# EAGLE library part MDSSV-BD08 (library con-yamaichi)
YAMAICHI CONNECTOR
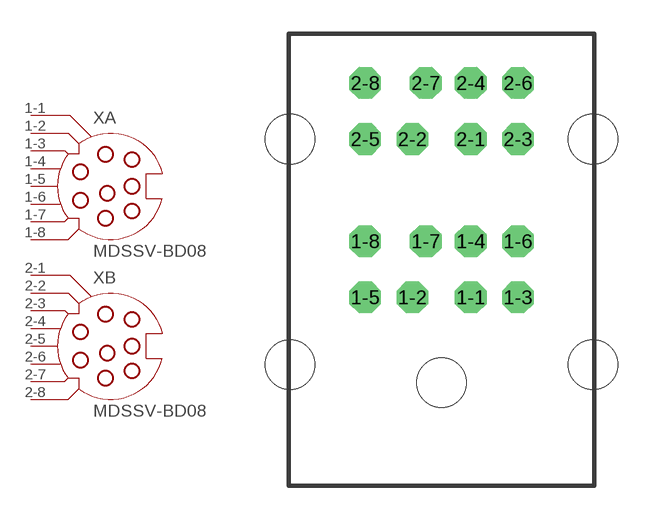
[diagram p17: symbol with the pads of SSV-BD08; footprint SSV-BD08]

Designator prefix X; gates A=SSV-BC08 B=SSV-BC08

## MDSSV-BD08 (OC_FARNELL: unknown; OC_NEWARK: unknown)  [SSV-BD08]
1-1  A:1  pas
1-2  A:2  pas
1-3  A:3  pas
1-4  A:4  pas
1-5  A:5  pas
1-6  A:6  pas
1-7  A:7  pas
1-8  A:8  pas
2-1  B:1  pas
2-2  B:2  pas
2-3  B:3  pas
2-4  B:4  pas
2-5  B:5  pas
2-6  B:6  pas
2-7  B:7  pas
2-8  B:8  pas

## Footprint SSV-BD08 (pad centres in mm)
Mini Din YAMAICHI CONNECTOR
drill 0.9 octagon: 1-1 1.3,8.5; 1-2 -1.3,8.5; 1-3 3.4,8.5; 1-4 1.3,11; 1-5 -3.4,8.5; 1-6 3.4,11; 1-7 -0.7,11; 1-8 -3.4,11; 2-1 1.3,15.55; 2-2 -1.3,15.55; 2-3 3.4,15.55; 2-4 1.3,18.05; 2-5 -3.4,15.55; 2-6 3.4,18.05; 2-7 -0.7,18.05; 2-8 -3.4,18.05
hole 2.2 at -6.75,5.5
hole 2.2 at 0,4.7
hole 2.2 at 6.75,5.5
hole 2.2 at -6.75,15.55
hole 2.2 at 6.75,15.55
